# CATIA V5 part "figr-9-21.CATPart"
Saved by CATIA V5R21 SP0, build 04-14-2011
Part number: Part3
Bounding box of the stored display mesh (mm): x -112 to 0, y -101.683 to 104.654, z -80.304 to 44.557
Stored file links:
  D:\CATIA V5R21 E-RESOURCES\CATIA-V5R21\catia-v5r21-prt\c09-catia-v5r20-prt\c09-catia-v5r21-figr-9-21.CATPart
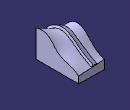
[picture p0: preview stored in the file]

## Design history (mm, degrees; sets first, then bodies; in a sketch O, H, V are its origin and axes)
Set1
  Plane1: type Offset, RefPlane yz-plane, Offset -112
  Plane2: type Offset, RefPlane yz-plane, Offset -63
  Plane3: type Normal, Curve Sketch4, RefPoint vertex of Sketch4
Body1 (main body)
  Sketch1 on yz-plane, origin (0, 0, 0), H (0, 1, 0), V (0, 0, 1)
    spline S1 through (-92.6897, 40.1119) (-30, 30) (10, -10) (60, -30) (97.3103, -50.3041)
    line L1 (97.3103, -50.3041) -> (97.3103, -80.3041)
    line L2 (97.3103, -80.3041) -> (-92.6897, -80.3041)
    line L3 (-92.6897, -80.3041) -> (-92.6897, 40.1119)
    point P3 (-92.6897, 40.1119)
    point P4 (97.3103, -50.3041)
    point P5 (-92.6897, 40.1119)
    point P6 (97.3103, -50.3041)
    vertical: L1 V, L3 V
    horizontal: L2 H
    coincidence: P5 P3, P6 P4
  Sketch2 on Plane1, origin (-112, 0, 0), H (0, 1, 0), V (0, 0, 1)
    spline S1 through (-90, -30) (-70, 10) (-20, 40) (40, 0) (100, -40)
    line L1 (100, -40) -> (100, -80)
    line L2 (100, -80) -> (-90, -80)
    line L3 (-90, -80) -> (-90, -30)
    point P3 (-90, -30)
    point P4 (100, -40)
    point P5 (40, 0)
    point P6 (-90, -30)
    point P7 (100, -40)
    coincidence: P5 H, P6 P3, P7 P4
    vertical: L1 V, L3 V
    horizontal: L2 H
  Loft1: Sections (Sketch1; Sketch2)
  Sketch3 on Plane3, origin (0, -40.1726, -44.9298), H (1, 0, 0), V (0, -0.7455, 0.6665)
    point P1 (-63, 68.4187)
    line L1 (-63, 68.4187) -> (-75.2117, 62.4925)
    line L2 (-75.2117, 62.4925) -> (-79.6266, 71.5898)
    line L3 (-79.6266, 71.5898) -> (-57.1205, 82.5119)
    line L4 (-57.1205, 82.5119) -> (-52.7056, 73.4145)
    point P5 (-52.7056, 73.4145)
    line L5 (-52.7056, 73.4145) -> (-63, 68.4187)
    reference projected point E1 (-63, 68.4187) from vertex of Sketch4
    perpendicularity: L2 L1
    parallelism: L3 L1, L4 L2, L5 L1
    coincidence: P5 L1, P1 E1
  Sketch4 on Plane2, origin (-63, 0, 0), H (0, 1, 0), V (0, 0, 1)
    intersected curve E1 from face of Loft1
  Rib1: profile Sketch3, centre curve Sketch4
